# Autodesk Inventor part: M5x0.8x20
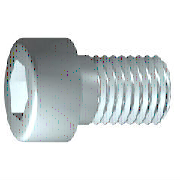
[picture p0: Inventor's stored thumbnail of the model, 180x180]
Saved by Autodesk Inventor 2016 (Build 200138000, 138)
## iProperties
IsCustomPart: 0
Created: 2015-11
Part Number: M5x0.8x20
Material: 스테인리스강
Description: 6각머리 태핑 나사
Document SubType Name: Modeling
Standard: KS B 1003
Designer: mdu
Standards Organization: KS
Language: ko-KR
Size Designation: M 5 x 20
Categories: <MemberInstance><Categories><Category DisplayName="조임쇠" InternalName="e4da775c-781d-43d5-af7c-5136215cf5a6" Mnemonic="FSTN"><Category DisplayName="볼트" InternalN
Density: 8.08 g/cm^3
Mass: 5.10181 g
Surface Area: 5.88237 cm^2
Volume: 0.631412 cm^3
Appearance: 반광택
Author: mdu
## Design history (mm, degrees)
sketch "스케치1"
  geometry: L1 (-1.167, 0)-(20, 0); L2 (20, 0)-(20, 2.5); L3 (20, 2.5)-(2, 2.5); L4 (2, 2.5)-(1.509, 2.5); L5 (1.509, 2.5)-(0, 2.5); L6 (0, 2.5)-(0, 4.25); L7 (0, 4.25)-(-5, 4.25); L8 (-5, 4.25)-(-5, 2.309); L9 (-5, 2.309)-(-2.5, 2.309); L10 (-2.5, 2.309)-(-1.167, 0); L11 (-10, 0)-(25, 0) reference; L12 (0, -0.85)-(0, 5.1) reference; L13 (2, 2.5)-(0, 2.5)
  constraints: 22 end point, 6 parallel, 2 collinear, 2 perpendicular, 1 horizontal, 1 point on line
  dimensions: "d1" = 18 distance from line of L3.end L2 (= GEL); "d2" = 0.49086 distance of L4.end L3.end (computed from GAL); "d3" = 5 distance between parallel lines of L8 L6 (= KOH); "d4" = 2.5 distance of L8.end L9.end (= INTI); "d5" = 60 deg angle of L10 L1; "d6" = 5 diameter of L3 L1 (= GD); "d7" = 5 diameter of L5 L1 (= BDM); "d8" = 4.6188 diameter of L9 L1 (= 1.1547 x SW); "d9" = 8.5 diameter of L7 L1 (= KOD); "d26" = 20 distance between parallel lines of L12 L2 (= NLG)
revolve "본체" sketch "스케치1" stored, may be unused: angle "d10" = 90 deg
sketch "스케치2"
  geometry: L1 (0, -5.95)-(0, 5.95) reference; L2 (-5.95, 0)-(5.95, 0) reference; L3 (2.309, 0)-(1.155, -2); L4 (1.155, -2)-(-1.155, -2); L5 (-1.155, -2)-(-2.309, 0); L6 (-2.309, 0)-(-1.155, 2); L7 (-1.155, 2)-(1.155, 2); L8 (1.155, 2)-(2.309, 0); 2 further points
  constraints: 12 end point, 1 coincident, 1 horizontal alignment, 1 point on line, 12 other
extrude "슬롯" join sketch "스케치2" stored distance "d11" = 10; taper "d12" = 0 deg
workplane "Work Plane1"
fillet "Fillet2" dims "d30" = 0.1 (= R)
body "Solid1"
fillet "모깎기1" dims "d17" = 0.5 (= RR)
feature "스레드" dims "d13" = 18 (= GEL), "d14" = 0
chamfer "모따기1" distance "d15" = 0.49076 (= -0.5 x SPD + 0.5 x GD); stored, may be unused: second distance "d16" = 0.49076 (= GUL), angle "d27" = 45 deg
other parameters: "GD" = 5 (= NND) [user parameter; used in 2 equation terms], "NLG" = 20 [user parameter; used in 1 equation term], "GEL" = 18 [user parameter; used in 2 equation terms], "KOD" = 8.5 [user parameter; used in 1 equation term], "KOH" = 5 [user parameter; used in 1 equation term], "INTI" = 2.5 [user parameter; used in 1 equation term], "GAL" = 0.49076 (= 0.61345 x PTC) [user parameter; used in 1 equation term], "GUL" = 0.49076 (= 0.61345 x PTC) [user parameter; used in 1 equation term], "BDM" = 5 (= NND) [user parameter; used in 1 equation term], "SW" = 4 [user parameter; used in 2 equation terms], "RR" = 0.5 [user parameter; used in 1 equation term], "SPD" = 4.01848 (= NND - 1.2269 x PTC) [user parameter; used in 1 equation term], "d19" = 0, "d28" = 0, "d29" = 0, "R" = 0.1 [user parameter; used in 1 equation term], "PHH" = 0.2 [user parameter], "GD1" = 4.01848 (= THREADDIA - 1.2269 x PTC) [user parameter], "THREADDIA" = 5 [user parameter; used in 1 equation term], "FAWI" = 45 deg [user parameter], "TPU" = 12.5 (computed from PTC) [user parameter], "PTC" = 0.8 [user parameter; used in 5 equation terms], "NND" = 5 [user parameter; used in 3 equation terms], "TOA" = 30 deg [user parameter], "E0" = 4.62 (= 1.155 x SW) [user parameter]
